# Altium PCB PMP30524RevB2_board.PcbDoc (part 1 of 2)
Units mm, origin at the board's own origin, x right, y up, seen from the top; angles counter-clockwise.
Board outline 60.96 x 53.34 mm, 2 copper layers (Top Layer, Bottom Layer), stack 1.575 mm thick; 66 components, 30 nets, 147 pads, 87 vias.
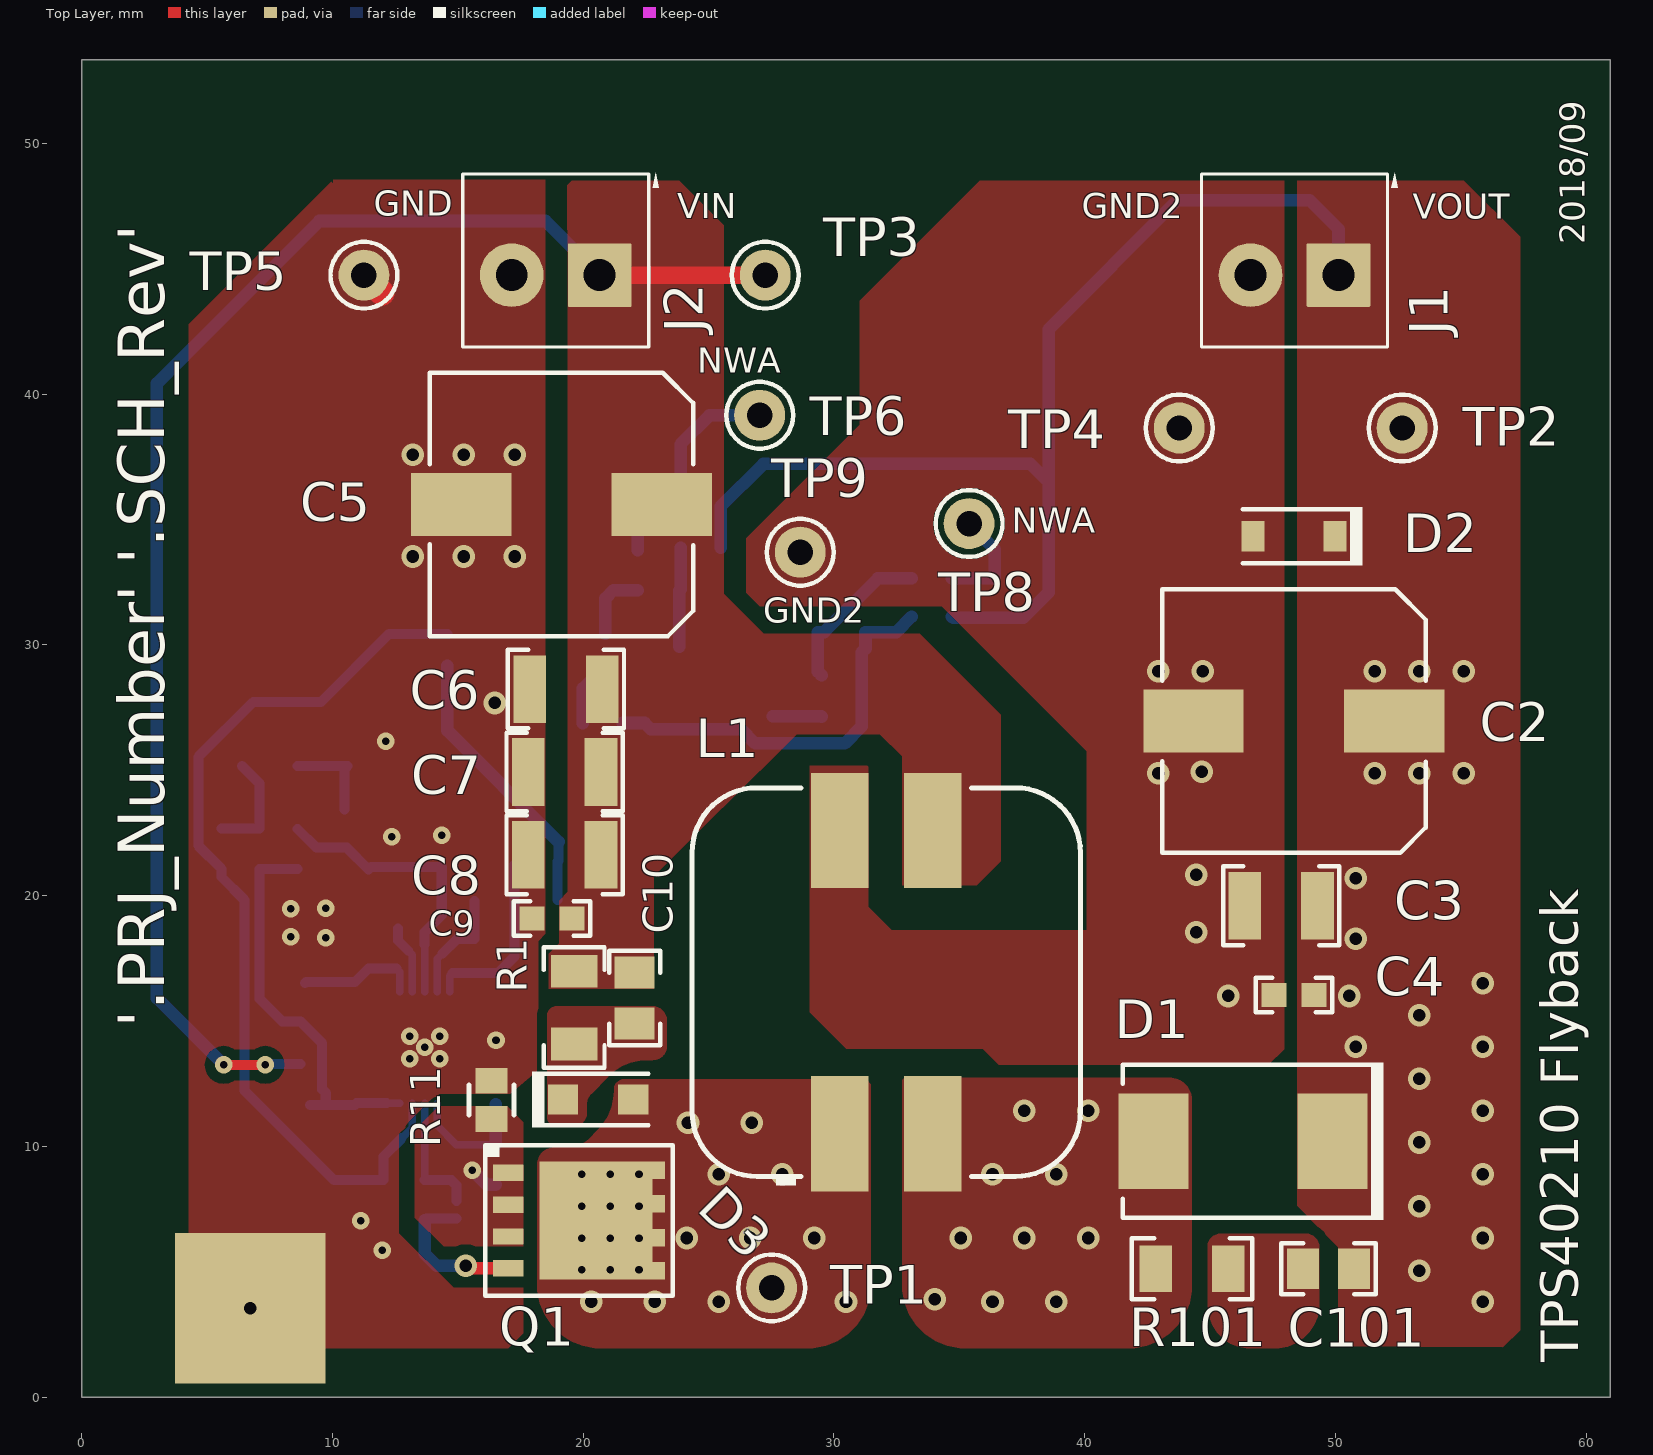
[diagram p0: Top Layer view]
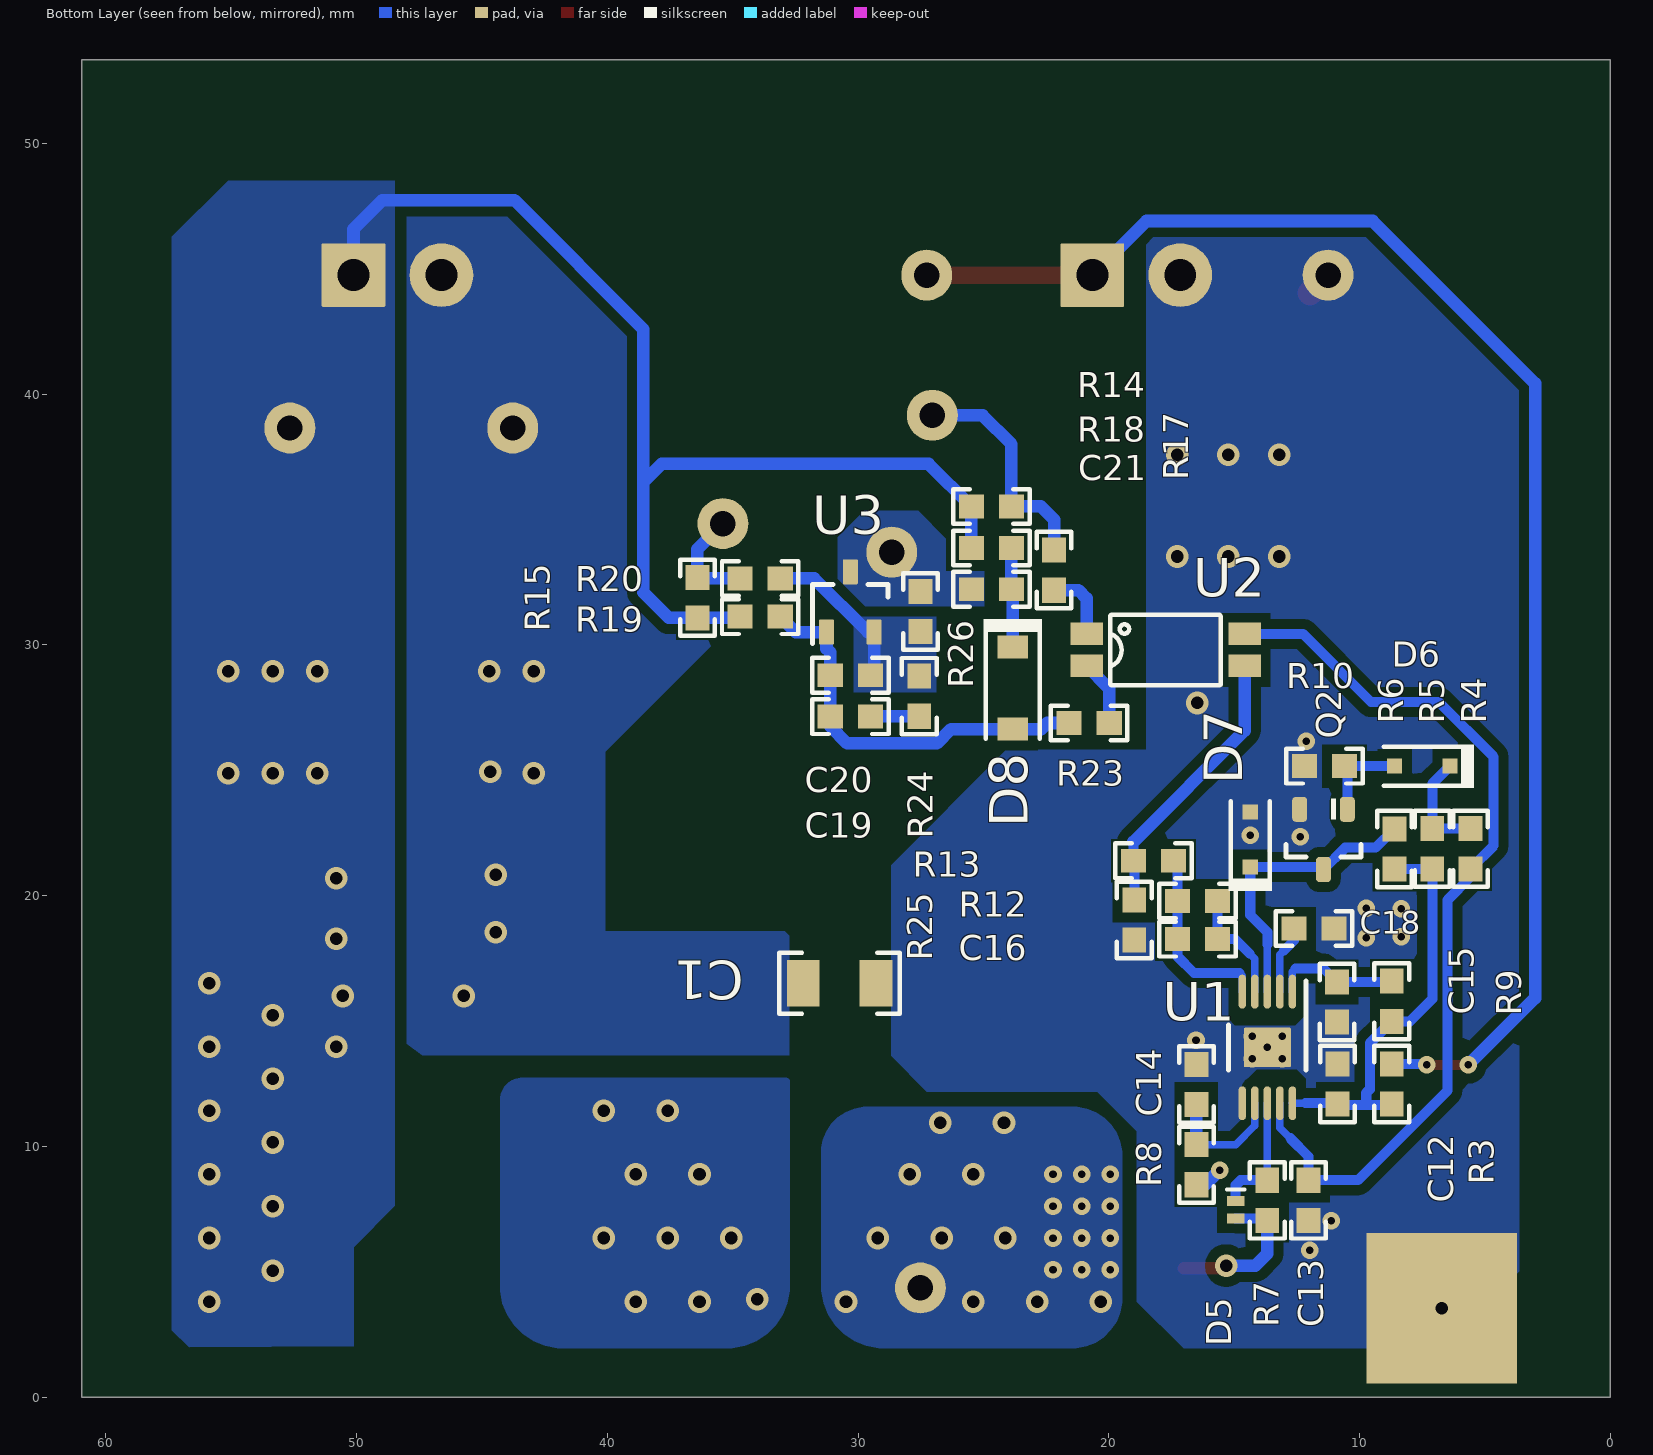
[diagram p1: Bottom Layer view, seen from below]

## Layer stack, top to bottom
Top Solder: solder mask 0.0102, Solder Resist, Dk 3.5
Top Layer: signal copper 0.0356
Dielectric1: core 1.5037, FR-4, Dk 4.8
Bottom Layer: signal copper 0.0356
Bottom Solder: solder mask 0.0102, Solder Resist, Dk 3.5

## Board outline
0,0 0,53.34 60.96,53.34 60.96,0

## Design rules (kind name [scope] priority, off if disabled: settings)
AcuteAngle [All] p1: minimum=4.50000000000000E+0001 checktracksonly=FALSE
AssemblyTestPointUsage [All] p1: valid=2
BoardOutlineClearance BoardOutlineClearance_MountingHoles [OnCopper and InComponentClass('Mounting Holes')] p1: gap=1.016 ignorepadtopadclearanceinfootprint=FALSE
BoardOutlineClearance BoardOutlineClearance_Poly [OnCopper and IsPoly] p2: gap=0.635 ignorepadtopadclearanceinfootprint=FALSE
BoardOutlineClearance [OnCopper and Not InComponentClass('Logo') and not InComponentClass('FiducialMark') and not InRegion(1000,500,4000,800) and not InPoly] p3: gap=1.905 ignorepadtopadclearanceinfootprint=FALSE
Clearance Clearance_Keepouts [((IsTrack Or IsArc) And Not InPoly) And IsFree and IsKeepOut vs ((IsTrack Or IsArc) And Not InPoly) And IsFree and IsKeepOut] p1: gap=0 ignorepadtopadclearanceinfootprint=FALSE
Clearance Clearance_Poly [InPolygon] p2: gap=0.4 ignorepadtopadclearanceinfootprint=FALSE except(0: Arc-Hole Track-Hole SMDPad-Hole THPad-Hole Via-Hole Fill-Hole Poly-Hole Region-Hole Text-Hole)
Clearance Clearance_FiducialMark [IsKeepOut and InComponentClass('FiducialMark') vs IsPad and InComponentClass('FiducialMark')] p3: gap=0 ignorepadtopadclearanceinfootprint=FALSE
Clearance [All] p4: gap=0.2 ignorepadtopadclearanceinfootprint=FALSE except(0: Arc-Hole Track-Hole SMDPad-Hole THPad-Hole Via-Hole Fill-Hole Poly-Hole Region-Hole Text-Hole)
ComponentClearance ComponentClearance_MountingHoles_FiducialMarks [InComponentClass('Mounting Holes') vs InComponentClass('FiducialMark')] p1: gap=1.27 collisioncheckmode=3 verticalgap=0.254 showdistances=FALSE
ComponentClearance ComponentClearance_Shunt [InComponentClass('Header') vs InComponentClass('Shunt')] p2: gap=0 collisioncheckmode=3 verticalgap=0 showdistances=FALSE
ComponentClearance ComponentClearance_Logo [InComponentClass('Logo')] p3: gap=1.27 collisioncheckmode=3 verticalgap=0.254 showdistances=FALSE
ComponentClearance ComponentClearance_ScrewToNut [(HasFootprint('NY PMS 440 0025 PH')) vs (HasFootprint('Keystone_1902C'))] p4: gap=0.127 collisioncheckmode=3 verticalgap=0.254 showdistances=FALSE
ComponentClearance ComponentClearance_MountingHoles [InComponentClass('Mounting Holes')] p5: gap=6.35 collisioncheckmode=3 verticalgap=2540 showdistances=FALSE
ComponentClearance ComponentClearance_SmallPassives [HasFootprint('0201*') or HasFootprint('0402*') or HasFootprint('0508') or HasFootprint('0603*') or HasFootprint('0612') or HasFootprint('0805*') or HasFootprint('0815*') or HasFootprint('0830*') or HasFootprint('1206*') or HasFootprint('1210*') or HasFootprint('1808*') or HasFootprint('1812*') or HasFootprint('1825*') or HasFootprint('2010*') or HasFootprint('2220*') or HasFootprint('2225*') or HasFootprint('2512*') or HasFootprint('2728*') or HasFootprint('3518*') or HasFootprint ('X1-DFN1006-2') vs HasFootprint('0201*') or HasFootprint('0402*') or HasFootprint('0508') or HasFootprint('0603*') or HasFootprint('0612') or HasFootprint('0805*') or HasFootprint('0815*') or HasFootprint('0830*') or HasFootprint('1206*') or HasFootprint('1210*') or HasFootprint('1808*') or HasFootprint('1812*') or HasFootprint('1825*') or HasFootprint('2010*') or HasFootprint('2220*') or HasFootprint('2225*') or HasFootprint('2512*') or HasFootprint('2728*') or HasFootprint('3518*') or HasFootprint ('X1-DFN1006-2')] p6: gap=0.38 collisioncheckmode=3 verticalgap=0.254 showdistances=FALSE
ComponentClearance ComponentClearance_THtoSMT [IsThruComponent vs IsSMTComponent] p7: gap=1.016 collisioncheckmode=3 verticalgap=0.762 showdistances=FALSE
ComponentClearance ComponentClearance_THtoTH [IsThruComponent vs IsThruComponent] p8: gap=0.762 collisioncheckmode=3 verticalgap=0.762 showdistances=FALSE
ComponentClearance [All] p9: gap=0.762 collisioncheckmode=3 verticalgap=0.254 showdistances=FALSE
DiffPairsRouting [All] p1: maxlimit=2.54 minlimit=0.254 mostfreqgap=0.254 toplayer_minwidth=0.381 toplayer_maxwidth=0.381 toplayer_prefwidth=0.381 bottomlayer_minwidth=0.381 bottomlayer_maxwidth=0.381 bottomlayer_prefwidth=0.381 maxuncoupledlength=25.4
FabricationTestPointUsage TestPointUsage [All] p1: valid=2 allowmultiple=FALSE
FabricationTestpoint Testpoint [All] p1: side=3 testpointundercomponent=TRUE minsize=1.016 maxsize=2.54 preferedsize=1.524 minholesize=0 maxholesize=1.016 preferedholesize=0.813 testpointgrid=0.025 allowsidetop=TRUE allowsidebottom=TRUE usegrid=TRUE gridtolerance=0
FanoutControl Fanout_LCC [IsLCC] p1: bgadir=Out bgaviamode=Centered fanoutstyle=Auto fanoutdirection=Alternating viagrid=0.025 // Fanout_LCC (Default Rule)
FanoutControl Fanout_BGA [IsBGA] p2: bgadir=Out bgaviamode=Centered fanoutstyle=Auto fanoutdirection=Alternating viagrid=0.025 // Fanout_BGA (Default Rule)
FanoutControl Fanout_Default [All] p4: bgadir=Out bgaviamode=Centered fanoutstyle=Auto fanoutdirection=Alternating viagrid=0.025 // Fanout_Default (Default Rule)
FanoutControl Fanout_Small [(CompPinCount < 5)] p5: bgadir=Out bgaviamode=Centered fanoutstyle=Auto fanoutdirection=OutThenIn viagrid=0.025 // Fanout_Small (Default Rule)
HoleSize [All] p1: absolutevalues=TRUE maxlimit=6.375 minlimit=0.3 maxpercent=80.000 minpercent=20.000
MinimumAnnularRing MinimumAnnularRing_ThermalPadVias [IsVia and InAnyComponent] p1: minimumring=0.15
MinimumAnnularRing [All] p2: minimumring=0.2
MinimumSolderMaskSliver MinimumSolderMaskSliver_Logo [InComponentClass('Logo') vs InComponentClass('Logo')] p1: minsoldermaskwidth=0.018
MinimumSolderMaskSliver [All] p2: minsoldermaskwidth=0.1
PlaneConnect [All] p1: planeconnectstyle=Relief reliefexpansion=0.254 reliefentries=4 reliefconductorwidth=0.254 reliefairgap=0.254
PolygonConnect [All] p1: connectstyle=Direct reliefconductorwidth=0.254 reliefentries=4 polygonreliefangle="90 Angle" airgapwidth=0.254
RoutingVias ThermalPadVias [IsVia and InAnyComponent] p1: holewidth=0.3 width=0.7 viastyle="Through Hole" minholewidth=0.3 minwidth=0.6 maxholewidth=0.6 maxwidth=1.6
RoutingVias [All] p2: holewidth=0.3 width=0.7 viastyle="Through Hole" minholewidth=0.3 minwidth=0.6 maxholewidth=1.016 maxwidth=2
SilkToBoardRegionClearance [Not ((IsComment or IsDesignator) And (Hide <> 'False')) and not InRegion(1000,500,4000,800)] p1:
SilkToSilkClearance SilkToSilkClearance_Pb-FreeLogo [(HasFootprint('Pb-Free_Overlay_Medium') OR HasFootprint('Pb-Free_Overlay_Small')) vs (HasFootprint('Pb-Free_Overlay_Medium') OR HasFootprint('Pb-Free_Overlay_Small'))] p1: silktosilkclearance=0
SilkToSilkClearance [All] p2: silktosilkclearance=0.102
SilkToSolderMaskClearance SilkToComponentPadClearance [(IsPad or IsFill or IsRegion) and InAnycomponent] p1: minsilkscreentomaskgap=0.127 clearancetoexposedcopper=TRUE
SilkToSolderMaskClearance "Silk to Solder Mask Opening" [All] p2: minsilkscreentomaskgap=0.102 clearancetoexposedcopper=FALSE
SolderMaskExpansion [All] p1: expansion=0.05
Width [All] p1: maxlimit=2.54 minlimit=0.152 preferedwidth=0.254 checkconnectedcopper=TRUE
15 further rules are at their usual default settings.

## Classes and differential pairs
net class U3_Nets: GND2 NetC19_2 NetC20_2
net class U2_Nets: NetR13_1 NetR17_1 NetR23_2 VBP
net class U1_Nets: GND NetC12_1 NetC14_1 NetC15_1 NetC16_1 NetC16_2 NetC18_1 NetD5_1 NetD7_1 VBP
net class TP9_Nets: GND2
net class TP8_Nets: NetR15_2
net class TP6_Nets: NetR14_1
net class TP5_Nets: GND
net class TP4_Nets: GND2
net class TP3_Nets: NetC5_1
net class TP2_Nets: VOUT
net class TP1_Nets: NetD3_2
net class R101_Nets: NetC101_2 NetD1_2
net class R26_Nets: GND2 NetC20_2
net class R25_Nets: GND NetR13_1
net class R24_Nets: NetC19_1 NetC20_2
net class R23_Nets: NetC19_2 NetR23_2
net class R20_Nets: NetC20_2 NetR15_2
net class R19_Nets: NetC19_2 VOUT
net class R18_Nets: NetC21_1 VOUT
net class R17_Nets: NetR14_1 NetR17_1
net class R15_Nets: NetR15_2 VOUT
net class R14_Nets: NetR14_1 VOUT
net class R13_Nets: NetC16_2 NetR13_1
net class R12_Nets: NetC16_1 NetC16_2
net class R11_Nets: GND NetQ1_1
net class R10_Nets: GND NetD6_2
net class R9_Nets: NetC12_1 NetC15_1
net class R8_Nets: NetC14_1 NetQ1_1
net class R7_Nets: NetD5_1 NetD5_2
net class R6_Nets: NetC12_1 NetD7_1
net class R5_Nets: NetC12_1 NetD6_1
net class R4_Nets: NetD6_1 VBP
net class R3_Nets: NetC5_1 NetC12_1
net class R1_Nets: NetC5_1 NetC10_2
net class Q2_Nets: GND NetD6_2 NetD7_1
net class Q1_Nets: NetD3_2 NetD5_2 NetQ1_1
net class L1_Nets: GND2 NetC5_1 NetD1_2 NetD3_2
net class J2_Nets: GND NetC5_1
net class J1_Nets: GND2 VOUT
net class D8_Nets: NetC19_2 NetC21_1
net class D7_Nets: GND NetD7_1
net class D6_Nets: NetD6_1 NetD6_2
net class D5_Nets: NetD5_1 NetD5_2
net class D3_Nets: NetC10_2 NetD3_2
net class D2_Nets: GND2 VOUT
net class D1_Nets: NetD1_2 VOUT
net class C101_Nets: NetC101_2 VOUT
net class C21_Nets: GND2 NetC21_1
net class C20_Nets: NetC19_2 NetC20_2
net class C19_Nets: NetC19_1 NetC19_2
net class C18_Nets: GND NetC18_1
net class C16_Nets: NetC16_1 NetC16_2
net class C15_Nets: GND NetC15_1
net class C14_Nets: GND NetC14_1
net class C13_Nets: GND VBP
net class C12_Nets: GND NetC12_1
net class C10_Nets: NetC5_1 NetC10_2
net class C9_Nets: GND NetC5_1
net class C8_Nets: GND NetC5_1
net class C7_Nets: GND NetC5_1
net class C6_Nets: GND NetC5_1
net class C5_Nets: GND NetC5_1
net class C4_Nets: GND2 VOUT
net class C3_Nets: GND2 VOUT
net class C2_Nets: GND2 VOUT
net class C1_Nets: GND GND2

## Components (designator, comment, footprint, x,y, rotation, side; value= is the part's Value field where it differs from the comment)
C1 "GRM31BR73A102KW01L" 1206 30.734,16.51 r180 bottom value=1000pF
C2 "EEHZC1V271P" SM_RADIAL_10BMM 48.341,26.968 r180 top value=270uF
C3 "GRM32ER71H106KA12L" 1210_270 47.833,19.602 r180 top value=10uF
C4 "GCM188R71H104KA57D" 0603 48.341,16.046 r180 top value=0.1uF
C5 "EEHZC1H101P" SM_RADIAL_10BMM 19.131,35.604 r180 top value=100uF
C6 "GRM32ER71H106KA12L" 1210_270 19.311,28.238 r180 top value=10uF
C7 "GRM32ER71H106KA12L" 1210_270 19.258,24.936 r180 top value=10uF
C8 "GRM32ER71H106KA12L" 1210_270 19.258,21.634 r180 top value=10uF
C9 "GCM188R71H104KA57D" 0603 18.75,19.094 r180 top value=0.1uF
C10 "GRM21BR72A103MA01L" 0805_HV 22.052,15.919 r270 top value=0.01uF
C12 "GRM188R71E105KA12D" 0603 10.876,12.49 r90 bottom value=1uF
C13 "GRM188R71C105KA12D" 0603 12.035,7.855 r270 bottom value=1uF
C14 "GRM188R71H221KA01D" 0603 16.506,12.476 r90 bottom value=220pF
C15 "GRM1885C1H471JA01D" 0603 10.9,15.762 r270 bottom value=470pF
C16 "GRM1885C1H101JA01D" 0603 16.466,18.269 r0 bottom value=100pF
C18 "GRM188R71C474KA88D" 0603 11.82,18.69 r180 bottom value=0.47uF
C19 "GRM188R71E333KA01D" 0603 30.307,27.141 r0 bottom value=0.033uF
C20 "GRM1885C1H470JA01D" 0603 30.307,28.792 r180 bottom value=47pF
C21 "GRM188R71C105KA12D" 0603 24.681,32.221 r0 bottom value=1uF
C101 "GRM2165C2A101JA01D" 0805_HV 49.723,5.124 r180 top value=100pF
D1 "B3100-13-F" SMC 46.309,10.204 r180 top value=100V
D2 "MMSZ5254B-7-F" SOD-123 48.341,34.334 r180 top value=27V
D3 "BAT46WH,115" SOD-123F 20.597,11.87 r0 top value=100V
D5 "BAT54LP-7" X1-DFN1006-2 14.94,7.484 r270 bottom value=30V
D6 "MMSZ5233BS-7-F" SOD-323 7.502,25.167 r0 bottom value=6V
D7 "MMSZ5233BS-7-F" SOD-323 14.36,22.246 r90 bottom value=6V
D8 "MMSD914" SOD-123 23.83,28.284 r270 bottom value=100V
J1 "ED555/2DS" TERM_BLK_ED555-2DS 50.119,44.748 r180 top
J2 "ED555/2DS" TERM_BLK_ED555-2DS 20.655,44.748 r180 top
L1 "MSD1514-153MEB" MSD1514 32.085,16.554 r90 top value=15uH
Q1 "BSC070N10NS5ATMA1" PG-TDSON-8 19.835,7.044 r0 top value=100V
Q2 "MMBT2222A" SOT-23 11.439,22.246 r270 bottom value=0.3V
R1 "CRCW1206100KJNEA" 1206 19.639,15.538 r90 top value=100k
R3 "CRCW060310R0FKEA" 0603 8.717,12.49 r90 bottom value=10.0
R4 "CRCW0603249KFKEA" 0603 5.575,21.873 r270 bottom value=249k
R5 "CRCW060320K0FKEA" 0603 7.099,21.873 r270 bottom value=20.0k
R6 "CRCW060320K0FKEA" 0603 8.611,21.865 r270 bottom value=20.0k
R7 "CRCW060310R0FKEA" 0603 13.678,7.855 r90 bottom value=10.0
R8 "CRCW06031K00FKEA" 0603 16.506,9.273 r270 bottom value=1.00k
R9 "CRCW0603200KFKEA" 0603 8.717,15.792 r270 bottom value=200k
R10 "CRCW0603100KFKEA" 0603 11.401,25.167 r180 bottom value=100k
R11 "WSLP0805R0200FEB" WSLP0805 16.337,11.855 r270 top value=0.02
R12 "CRCW060320K0FKEA" 0603 16.466,19.793 r180 bottom value=20.0k
R13 "CRCW06034K99FKEA" 0603 18.222,21.393 r180 bottom value=4.99k
R14 "CRCW060349R9FKEA" 0603 24.681,35.523 r0 bottom value=49.9
R15 "CRCW060349R9FKEA" 0603 36.403,31.882 r90 bottom value=49.9
R17 "CRCW06034K99FKEA" 0603 22.183,32.983 r90 bottom value=4.99k
R18 "CRCW060349K9FKEA" 0603 24.681,33.872 r0 bottom value=49.9k
R19 "CRCW060320K0FKEA" 0603 33.901,31.129 r0 bottom value=20.0k
R20 "CRCW060349K9FKEA" 0603 33.901,32.653 r0 bottom value=49.9k
R23 "CRCW06030000Z0EA" 0603 20.782,26.887 r180 bottom value=0
R24 "CRCW0603100KFKEA" 0603 27.555,27.956 r90 bottom value=100k
R25 "CRCW06031K00FKEA" 0603 18.984,19.031 r90 bottom value=1.00k
R26 "CRCW06035K76FKEA" 0603 27.513,31.332 r270 bottom value=5.76k
R101 "CRCW120610R0FKEA" 1206 44.277,5.124 r0 top value=10.0
TP1 "5002" Keystone5002 27.513,4.362 r0 top
TP2 "5000" Keystone5000 52.659,38.652 r90 top value=Red
TP3 "5000" Keystone5000 27.259,44.748 r90 top value=Red
TP4 "5001" Keystone5001 43.769,38.652 r90 top value=Black
TP5 "5001" Keystone5001 11.257,44.748 r90 top value=Black
TP6 "5003" Keystone5003 27.038,39.16 r90 top
TP8 "5003" Keystone5003 35.387,34.842 r90 top
TP9 "5001" Keystone5001 28.656,33.699 r90 top value=Black
U1 "TPS40210" DGQ0010D_N 13.678,13.951 r270 bottom
U2 "TCMT1107" SOP-4 17.734,29.808 r180 bottom
U3 "TL431" DBZ0003A_N 30.307,31.713 r90 bottom

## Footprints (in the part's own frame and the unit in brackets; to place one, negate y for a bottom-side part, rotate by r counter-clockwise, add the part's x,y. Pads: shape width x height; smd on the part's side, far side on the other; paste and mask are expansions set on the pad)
0603 [mm] "0603 from SM-752 data"
  rect 1x0.95 smd: 1(-0.8,0) 2(0.8,0)
  silkscreen extent -1.52,-0.69 1.52,0.69, body extent -0.87,-0.47 0.87,0.47, height 1
0805_HV [mil] "0805 with 30mil clearance between pads"
  rect 50x63 smd: 1(-40,0) 2(40,0)
  silkscreen extent -74,-40 74,40, body extent -43,-29 43,29, height 57
1206 [mm] "1206 from SM-752 data"
  rect 1.3x1.85 smd: 1(-1.45,0) 2(1.45,0)
  silkscreen extent -2.4,-1.21 2.4,1.21, body extent -1.7,-0.9 1.7,0.9, height 1.35
1210_270 [mm] "1210"
  rect 1.3x2.7 smd: 1(-1.45,0) 2(1.45,0)
  silkscreen extent -2.32,-1.57 2.32,1.57, body extent -1.7,-1.35 1.7,1.35, height 2.7
DBZ0003A_N [mm] "SOT23, 3-Leads, Body 2.9x1.3mm, Pitch 0.95mm, Lead Span 2.4mm, IPC Medium Density"
  rrect17% 1x0.6 smd: 1(-1.2,0.95) 2(-1.2,-0.95) 3(1.2,0)
  silkscreen extent -1.65,-1.5 0.7,1.5, body extent -1.26,-1.46 1.26,1.46, height 0.98
DGQ0010D_N [mm] "TSSOP, 10-Leads, Body 3x3mm, Pitch 0.5mm, Thermal Pad 1.88x1.57mm, IPC Medium Density"
  rrect100% 1.35x0.3 smd: 1(-2.225,1) 2(-2.225,0.5) 3(-2.225,0) 4(-2.225,-0.5) 5(-2.225,-1) 6(2.225,-1) 7(2.225,-0.5) 8(2.225,0) 9(2.225,0.5) 10(2.225,1)
  rrect6% 1.57x1.88 smd: 11(0,0)
  silkscreen extent -2.65,-1.55 0.9,1.55, body extent -2.46,-1.5 2.46,1.5, height 1.1
Keystone5000 [mil] "For Keystone 500x miniature loop terminals"
  round 80 hole 40: 1(0,0)
  silkscreen extent -52,-52 52,52, body extent -49,-49 49,49, height 182
Keystone5001 [mil] "For Keystone 500x miniature loop terminals"
  round 80 hole 40: 1(0,0)
  silkscreen extent -52,-52 52,52, body extent -49,-49 49,49, height 182
Keystone5002 [mil] "For Keystone 500x miniature loop terminals"
  round 80 hole 40: 1(0,0)
  silkscreen extent -52,-52 52,52, body extent -49,-49 49,49, height 182
Keystone5003 [mil] "For Keystone 500x miniature loop terminals"
  round 80 hole 40: 1(0,0)
  silkscreen extent -52,-52 52,52, body extent -49,-49 49,49, height 182
MSD1514 [mm] "SMD, 4-Leads, Body 15x15mm"
  rect 4.6x2.3 smd: 1(-6.05,1.85) 2(-6.05,-1.85) 3(6.05,-1.85) 4(6.05,1.85)
  silkscreen extent -8.1,-7.75 7.75,7.75, body extent -7.81,-7.75 7.79,7.75, height 14.2
PG-TDSON-8 [mm] "Infineon recommended land pattern"
  rect 1.2x0.65 smd: 1(-2.825,1.905) 2(-2.825,0.635) 3(-2.825,-0.635) 4(-2.825,-1.905)
  rect 0.5x0.7 smd: 5(3.175,-2) 6(3.175,-0.675) 7(3.175,0.675) 8(3.175,2)
  rect 4.5x4.7 smd paste-2.25: 9(0.675,0)
  silkscreen extent -3.74,-3 3.74,3, body extent -3.17,-2.89 3.17,2.9, height 1.1
SM_RADIAL_10BMM [mm] "Nichicon 10x10"
  rect 4x2.5 smd: 1(-4,0) 2(4,0)
  silkscreen extent -5.25,-5.25 5.25,5.25, body extent -5.25,-5.25 5.25,5.25, height 10.5
SMC [mil] "Molded Diode, 2-Leads, Body 6.9x5.8mm, IPC Medium Density, based on OnSemi component dimensions and land patterns"
  rect 110x150 smd: 1(-140.49,0) 2(140.49,0)
  silkscreen extent -221,-124 189,123, body extent -156,-116 156,116, height 91
SOD-123 [mm] "On Semi recommended land pattern"
  rect 0.915x1.22 smd: 1(-1.637,0) 2(1.637,0)
  silkscreen extent -2.74,-1.17 2.03,1.17, body extent -1.93,-0.9 1.93,0.9, height 1.35
SOD-123F [mm] "NXP recommended land pattern"
  rect 1.2x1.2 smd paste-0.05: 1(-1.4,0) 2(1.4,0)
  silkscreen extent -2.64,-1.12 2.01,1.12, body extent -1.8,-0.85 1.8,0.85, height 1.2
SOD-323 [mm] "NXP recommended land pattern"
  rect 0.6x0.6 smd paste-0.05: 1(-1.1,0) 2(1.1,0)
  silkscreen extent -2.06,-0.86 1.53,0.86, body extent -1.3,-0.67 1.3,0.68, height 1.1
SOP-4 [mm] "Vishay Half Pitch Mini-Flat Package"
  rect 1.3x0.9 smd: 1(-3.15,0.635) 2(-3.15,-0.635) 3(3.15,-0.635) 4(3.15,0.635)
  silkscreen extent -2.2,-1.41 2.2,1.39, body extent -3.5,-1.4 3.5,1.4, height 2.12
SOT-23 [mm] "SOT23, 3-Leads, Body 2.9x1.3mm, Pitch 0.95mm, Lead Span 2.5mm, IPC Medium Density"
  rrect50% 1x0.6 smd: 1(-1.2,0.95) 2(-1.2,-0.95) 3(1.2,0)
  silkscreen extent -1.63,-1.5 0.7,1.5, body extent -1.16,-1.45 1.21,1.45, height 1
TERM_BLK_ED555-2DS [mil]
  rrect4% 100x100 hole 50: 1(0,0)
  round 100 hole 50: 2(138,0)
  silkscreen extent -93,-161 215,113, body extent -69,-150 207,106, height 323
WSLP0805 [mm] "Vishay"
  rect 1.02x1.27 smd: 1(-0.76,0) 2(0.76,0)
  silkscreen extent -0.6,-0.9 0.6,0.9, body extent -1.14,-0.76 1.14,0.76, height 0.64
X1-DFN1006-2 [mm] "DIODES, INC"
  rect 0.4x0.7 smd: 1(-0.35,0) 2(0.35,0)
  silkscreen extent -0.8,-0.35 -0.8,0.35, body extent -0.54,-0.34 0.54,0.34, height 0.53

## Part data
C1: "CAP, CERM, 1000 pF, 1000 V,+/- 10%, X7R, 1206", Cap_Case=1206, Manufacturer=MuRata, Supplier Part Number 1=490-3494-1-ND, TempCo=X7R, Tolerance_%=10, Value2=1000V, ValueDisplayed=1000pF
C2: "CAP, Polymer Hybrid, 270 µF, 35 V,+/- 20%, 20 ohm, 10x10 SMD", Manufacturer=Panasonic, Supplier Part Number 1=P15472CT-ND, Tolerance_%=20, Value1="20 ohm", Value2=35V, ValueDisplayed=270µF
C3 C6 C7 C8: "CAP, CERM, 10 µF, 50 V,+/- 10%, X7R, 1210", Cap_Case=1210, Manufacturer=MuRata, Supplier Part Number 1=490-6544-1-ND, TempCo=X7R, Tolerance_%=10, Value1=Unknown, Value2=50V, ValueDisplayed=10µF
C4 C9: "CAP, CERM, 0.1 µF, 50 V, +/- 10%, X7R, 0603", Cap_Case=0603, Manufacturer=MuRata, Supplier Part Number 1=490-4779-1-ND, TempCo=X7R, Tolerance_%=10, Value1="0.02 ohm", Value2=50V, ValueDisplayed=0.1µF
C5: "CAP, Polymer Hybrid, 100 µF, 50 V,+/- 20%, 28 ohm, 10x10 SMD", Manufacturer=Panasonic, Supplier Part Number 1=P15462CT-ND, Tolerance_%=20, Value1="28 ohm", Value2=50V, ValueDisplayed=100µF
C10: "CAP, CERM, 0.01 µF, 100 V, +/- 20%, X7R, 0805", Cap_Case=0805, Manufacturer=MuRata, Supplier Part Number 1=490-1653-1-ND, TempCo=X7R, Tolerance_%=20, Value1=Unknown, Value2=100V, ValueDisplayed=0.01µF
C12: "CAP, CERM, 1 µF, 25 V,+/- 10%, X7R, 0603", Cap_Case=0603, Manufacturer=MuRata, Supplier Part Number 1=490-5307-1-ND, TempCo=X7R, Tolerance_%=10, Value1=Unknown, Value2=25V, ValueDisplayed=1µF
C13 C21: "CAP, CERM, 1 µF, 16 V, +/- 10%, X7R, 0603", Cap_Case=0603, Manufacturer=MuRata, Supplier Part Number 1=490-3900-1-ND, TempCo=X7R, Tolerance_%=10, Value1="0.011 ohm", Value2=16V, ValueDisplayed=1µF
C14: "CAP, CERM, 220 pF, 50 V,+/- 10%, X7R, 0603", Cap_Case=0603, Manufacturer=MuRata, Supplier Part Number 1=490-1483-1-ND, TempCo=X7R, Tolerance_%=10, Value1=Unknown, Value2=50V, ValueDisplayed=220pF
C15: "CAP, CERM, 470 pF, 50 V, +/- 5%, C0G/NP0, 0603", Cap_Case=0603, Manufacturer=MuRata, Supplier Part Number 1=490-1443-1-ND, TempCo=C0G/NP0, Tolerance_%=5, Value1=Unknown, Value2=50V, ValueDisplayed=470pF
C16: "CAP, CERM, 100 pF, 50 V,+/- 5%, C0G/NP0, 0603", Cap_Case=0603, Manufacturer=MuRata, Supplier Part Number 1=490-1427-1-ND, TempCo=C0G/NP0, Tolerance_%=5, Value2=50V, ValueDisplayed=100pF
C18: "CAP, CERM, 0.47 µF, 16 V,+/- 10%, X7R, 0603", Cap_Case=0603, Manufacturer=MuRata, Supplier Part Number 1=490-3295-1-ND, TempCo=X7R, Tolerance_%=10, Value1=Unknown, Value2=16V, ValueDisplayed=0.47µF
C19: "CAP, CERM, 0.033 µF, 25 V,+/- 10%, X7R, 0603", Cap_Case=0603, Manufacturer=MuRata, Supplier Part Number 1=490-1521-1-ND, TempCo=X7R, Tolerance_%=10, Value2=25V, ValueDisplayed=0.033µF
C20: "CAP, CERM, 47 pF, 50 V,+/- 5%, C0G/NP0, 0603", Cap_Case=0603, Manufacturer=MuRata, Supplier Part Number 1=490-1419-1-ND, TempCo=C0G/NP0, Tolerance_%=5, Value2=50V, ValueDisplayed=47pF
C101: "CAP, CERM, 100 pF, 100 V,+/- 5%, C0G/NP0, 0805", Cap_Case=0805, Manufacturer=MuRata, Supplier Part Number 1=490-1599-1-ND, TempCo=C0G/NP0, Tolerance_%=5, Value2=100V, ValueDisplayed=100pF
D1: "Diode, Schottky, 100 V, 3 A, SMC", Manufacturer="Diodes Inc.", Supplier Part Number 1=B3100-FDICT-ND, Value1=3A, Value2=0.79V
D2: "Diode, Zener, 27 V, 500 mW, SOD-123", Manufacturer="Diodes Inc.", Power_W=0.5, Supplier Part Number 1=MMSZ5254B-FDICT-ND, Value1=0.5W
D3: "Diode, Schottky, 100 V, 0.25 A, SOD-123F", Manufacturer=Nexperia, Supplier Part Number 1=568-6016-1-ND, Value1=0.25A, Value2=0.85V
D5: "Diode, Schottky, 30 V, 0.2 A, 1.00x0.50x0.60mm", Manufacturer="Diodes Inc.", Supplier Part Number 1=BAT54LPDICT-ND, Value1=0.2A, Value2=1V
D6 D7: "Diode, Zener, 6 V, 200 mW, SOD-323", Manufacturer="Diodes Inc.", Power_W=0.2, Supplier Part Number 1=MMSZ5233BS-FDICT-ND, Value1=0.2W
D8: library part MMSD914T1G, "Diode, Switching, 100 V, 0.2 A, SOD-123", Manufacturer="ON Semiconductor", Supplier Part Number 1=MMSD914T1GOSCT-ND, Value1=0.2A, Value2=V
J1 J2: "Terminal Block, 6A, 3.5mm Pitch, 2-Pos, TH", Manufacturer="On-Shore Technology", Supplier Part Number 1=ED1514-ND
L1: library part MSD1514-103MEB, "Coupled inductor, 15 µH, 3.4Arms, 0.028 ohm, SMD", Manufacturer=Coilcraft, ValueDisplayed=15µH
Q1: "MOSFET, N-CH, 100 V, 80 A, PG-TDSON-8", Alternate Manufacturer=None, Manufacturer="Infineon Technologies", Supplier Part Number 1=BSC070N10NS5ATMA1CT-ND, Value1="? ohm", Value2="30 nC"
Q2: library part "MMBT2222A, Fairchild Semiconductor", "Transistor, NPN, 40V, 0.15A, SOT-23", Manufacturer="Fairchild Semiconductor", Supplier Part Number 1=MMBT2222AFSCT-ND, Value1=0.15A, Value2=300
R1: "RES, 100 k, 5%, 0.25 W, 1206", Manufacturer=Vishay-Dale, Power_W=0.25, Supplier Part Number 1=541-100KECT-ND, TempCo="200 ppm/C", Tolerance_%=5, Value1=5%, Value2=0.25W, Value_Code=100k
R3 R7: "RES, 10.0, 1%, 0.1 W, 0603", Manufacturer=Vishay-Dale, Power_W=0.1, Supplier Part Number 1=541-10.0HCT-ND, TempCo="100 ppm/C", Tolerance_%=1, Value1=1%, Value2=0.1W, Value_Code=10R0, ValueDisplayed=10.0
R4: "RES, 249 k, 1%, 0.1 W, 0603", Manufacturer=Vishay-Dale, Power_W=0.1, Supplier Part Number 1=541-249KHCT-ND, TempCo="100 ppm/C", Tolerance_%=1, Value1=1%, Value2=0.1W, Value_Code=249k
R5 R6 R12 R19: "RES, 20.0 k, 1%, 0.1 W, 0603", Manufacturer=Vishay-Dale, Power_W=0.1, Supplier Part Number 1=541-20.0KHCT-ND, TempCo="100 ppm/C", Tolerance_%=1, Value1=1%, Value2=0.1W, Value_Code=20k0, ValueDisplayed=20.0k
R8 R25: "RES, 1.00 k, 1%, 0.1 W, 0603", Manufacturer=Vishay-Dale, Power_W=0.1, Supplier Part Number 1=541-1.00KHCT-ND, TempCo="100 ppm/C", Tolerance_%=1, Value1=1%, Value2=0.1W, Value_Code=1k00, ValueDisplayed=1.00k
R9: "RES, 200 k, 1%, 0.1 W, 0603", Manufacturer=Vishay-Dale, Power_W=0.1, Supplier Part Number 1=541-200KHCT-ND, TempCo="100 ppm/C", Tolerance_%=1, Value1=1%, Value2=0.1W, Value_Code=200k
R10: "RES, 100k ohm, 1%, 0.1W, 0603", Manufacturer=Vishay-Dale, Power_W=0.1, Supplier Part Number 1=541-100KHCT-ND, TempCo="100 ppm/C", Tolerance_%=1, Value1=1%, Value2=0.1W, Value_Code=100k
R11: "RES, 0.02, 1%, 0.5 W, 0805", Manufacturer=Vishay-Dale, Power_W=0.5, Supplier Part Number 1=WSLPB-.02CT-ND, TempCo="75 ppm/C", Tolerance_%=1, Value1=1%, Value2=0.5W, Value_Code=R020, ValueDisplayed=0.02
R13 R17: "RES, 4.99 k, 1%, 0.1 W, 0603", Manufacturer=Vishay-Dale, Power_W=0.1, Supplier Part Number 1=541-4.99KHCT-ND, TempCo="100 ppm/C", Tolerance_%=1, Value1=1%, Value2=0.1W, Value_Code=4k99, ValueDisplayed=4.99k
R14 R15: "RES, 49.9, 1%, 0.1 W, 0603", Manufacturer=Vishay-Dale, Power_W=0.1, Supplier Part Number 1=541-49.9HCT-ND, TempCo="100 ppm/C", Tolerance_%=1, Value1=1%, Value2=0.1W, Value_Code=49R9, ValueDisplayed=49.9
R18 R20: "RES, 49.9 k, 1%, 0.1 W, 0603", Manufacturer=Vishay-Dale, Power_W=0.1, Supplier Part Number 1=541-49.9KHCT-ND, TempCo="100 ppm/C", Tolerance_%=1, Value1=1%, Value2=0.1W, Value_Code=49k9, ValueDisplayed=49.9k
R23: "RES, 0, 5%, 0.1 W, 0603", Manufacturer=Vishay-Dale, Power_W=0.1, Supplier Part Number 1=541-0.0GCT-ND, TempCo="200 ppm/C", Tolerance_%=5, Value1=5%, Value2=0.1W, Value_Code=0000, ValueDisplayed=0
R24: "RES, 100 k, 1%, 0.1 W, 0603", Manufacturer=Vishay-Dale, Power_W=0.1, Supplier Part Number 1=541-100KHCT-ND, TempCo="100 ppm/C", Tolerance_%=1, Value1=1%, Value2=0.1W, Value_Code=100k
R26: "RES, 5.76 k, 1%, 0.1 W, 0603", Manufacturer=Vishay-Dale, Power_W=0.1, Supplier Part Number 1=541-5.76KHCT-ND, TempCo="100 ppm/C", Tolerance_%=1, Value1=1%, Value2=0.1W, Value_Code=5k76, ValueDisplayed=5.76k
R101: "RES, 10.0, 1%, 0.25 W, 1206", Manufacturer=Vishay-Dale, Power_W=0.25, Supplier Part Number 1=541-10.0FCT-ND, TempCo="100 ppm/C", Tolerance_%=1, Value1=1%, Value2=0.25W, Value_Code=10R0, ValueDisplayed=10.0
TP1: "Test Point, Miniature, White, TH", Color=White, Manufacturer=Keystone, Supplier Part Number 1=36-5002-ND
TP2 TP3: "Test Point, Miniature, Red, TH", Manufacturer=Keystone, Supplier Part Number 1=5000K-ND
TP4 TP5 TP9: "Test Point, Miniature, Black, TH", Manufacturer=Keystone, Supplier Part Number 1=5001K-ND
TP6 TP8: "Test Point, Miniature, Orange, TH", Color=Orange, Manufacturer=Keystone, Supplier Part Number 1=36-5003-ND
U1: library part TPS40210QDGQRQ1, "4.5-V TO 52-V INPUT CURRENT MODE BOOST CONTROLLER, DGQ0010D", Alternate Manufacturer="Texas Instruments"
U2: "Optocoupler, 3.75 kV, 80-160% CTR, SMT", Manufacturer=Vishay-Semiconductor, Supplier Part Number 1=TCMT1107CT-ND, Voltage_Isolation_Vrms=3750V
U3: library part TL431AIDBZR, "Adjustable Precision Shunt Regulator, 34 ppm / degC, 100 mA, -40 to 85 degC, 3-pin SOT-23 (DBZ), Green (RoHS & no Sb/Br)", Alternate Manufacturer="Texas Instruments", Alternate PartNumber=Equivalent, Rating=Catalog, Supplier Part Number 1=296-17329-2-ND, Temp Coeff(Max)(ppm/ degree C)=92, Temp Coeff(Typ)(ppm/ degree C)=34

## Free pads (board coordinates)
  rect 6x6 hole 0.5: 1(6.731,3.556)

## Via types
v1: diameter 0.9, hole 0.5, Top Layer to Bottom Layer, 28 vias
v2: diameter 0.9, hole 0.5, Top Layer to Bottom Layer, tented top, 27 vias
v3: diameter 0.7, hole 0.3, Top Layer to Bottom Layer, 20 vias
v4: diameter 0.7, hole 0.3, Top Layer to Bottom Layer, tented bottom, 10 vias
v5: diameter 0.9, hole 0.5, Top Layer to Bottom Layer, tented bottom, 2 vias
